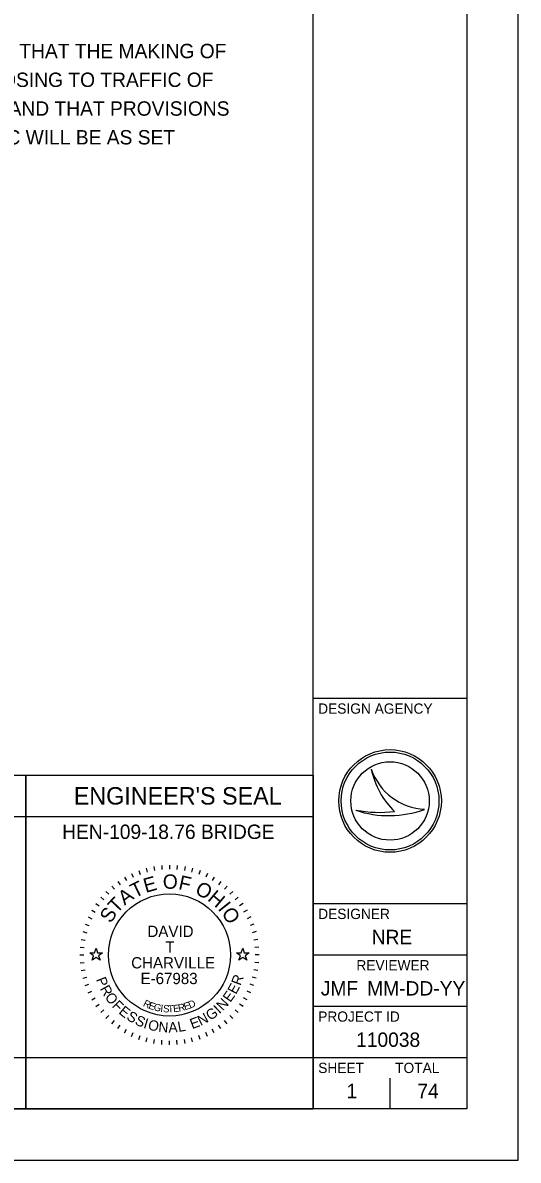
# Model space of a CAD drawing. Extents: x -6.2 to 37.4, y 0.2 to 22.2.
# Drawn here: x 28.75 to 33.58, y 0.21 to 11.29 of the extents above; entities that cross this region are included whole.
import ezdxf

# ---------------------------------------------------------------- set-up
doc = ezdxf.new("R2010")
doc.units = 0
for name, color, linetype in [('Default', 7, 'Continuous'), ('SH_Border', 7, 'Continuous'), ('SH_Cut_Line', 7, 'Continuous'), ('SH_Data', 7, 'Continuous'), ('SH_Text', 7, 'Continuous')]:
    doc.layers.add(name, color=color, linetype=linetype)

msp = doc.modelspace()

# ---------------------------------------------------------------- linework, layer by layer
at = {"layer": 'Default'}
for points in [[(29.404, 2.227), (29.451, 2.227), (29.466, 2.272), (29.48, 2.227), (29.527, 2.227), (29.489, 2.2), (29.504, 2.155), (29.466, 2.183), (29.428, 2.155), (29.442, 2.2)], [(30.834, 2.227), (30.881, 2.227), (30.896, 2.272), (30.91, 2.227), (30.957, 2.227), (30.919, 2.2), (30.934, 2.155), (30.896, 2.183), (30.858, 2.155), (30.872, 2.2)]]:
    msp.add_lwpolyline(points, close=True, dxfattribs=at)
at = {"layer": 'SH_Border'}
for p, q in [((31.581, 0.707), (31.581, 21.707)), ((31.581, 4.707), (33.081, 4.707)), ((31.581, 2.707), (33.081, 2.707)), ((31.581, 2.207), (33.081, 2.207)), ((31.581, 1.707), (33.081, 1.707)), ((31.581, 1.207), (33.081, 1.207))]:
    msp.add_line(p, q, dxfattribs=at)
msp.add_lwpolyline([(1.081, 21.707), (33.081, 21.707), (33.081, 0.707), (1.081, 0.707)], close=True, dxfattribs=at)
at = {"layer": 'SH_Cut_Line'}
msp.add_lwpolyline([(-0.419, 0.207), (33.581, 0.207), (33.581, 22.207), (-0.419, 22.207)], close=True, dxfattribs=at)
at = {"layer": 'SH_Data'}
for p, q in [((32.148, 4.017), (32.148, 4.017)), ((25.981, 3.957), (28.781, 3.957)), ((28.781, 3.957), (28.781, 0.707)), ((28.781, 0.707), (28.781, 3.957)), ((28.781, 3.957), (31.581, 3.957)), ((31.581, 3.957), (31.581, 0.707)), ((32.331, 3.707), (32.331, 3.707)), ((25.981, 3.557), (28.781, 3.557)), ((28.781, 3.557), (31.581, 3.557)), ((31.998, 3.617), (31.998, 3.617)), ((32.668, 3.626), (32.668, 3.626)), ((29.811, 3), (29.828, 2.964)), ((29.882, 3.03), (29.895, 2.992)), ((29.954, 3.053), (29.965, 3.014)), ((30.029, 3.069), (30.036, 3.03)), ((30.105, 3.079), (30.108, 3.039)), ((30.181, 3.082), (30.181, 3.042)), ((30.257, 3.079), (30.254, 3.039)), ((30.333, 3.069), (30.326, 3.03)), ((30.407, 3.053), (30.397, 3.014)), ((30.48, 3.03), (30.466, 2.992)), ((30.551, 3), (30.534, 2.964)), ((29.679, 2.924), (29.702, 2.891)), ((29.743, 2.965), (29.763, 2.931)), ((30.618, 2.965), (30.598, 2.931)), ((30.683, 2.924), (30.66, 2.891)), ((29.562, 2.826), (29.59, 2.798)), ((29.618, 2.878), (29.644, 2.847)), ((30.743, 2.878), (30.718, 2.847)), ((30.8, 2.826), (30.771, 2.798)), ((29.464, 2.709), (29.497, 2.686)), ((29.511, 2.77), (29.541, 2.744)), ((30.851, 2.77), (30.821, 2.744)), ((30.898, 2.709), (30.865, 2.686)), ((29.388, 2.577), (29.424, 2.56)), ((29.423, 2.645), (29.458, 2.625)), ((30.939, 2.645), (30.904, 2.625)), ((30.974, 2.577), (30.938, 2.56)), ((29.359, 2.507), (29.396, 2.493)), ((31.003, 2.507), (30.966, 2.493)), ((29.319, 2.359), (29.359, 2.352)), ((29.336, 2.434), (29.374, 2.424)), ((31.026, 2.434), (30.987, 2.424)), ((31.043, 2.359), (31.003, 2.352)), ((29.309, 2.284), (29.349, 2.28)), ((31.053, 2.284), (31.013, 2.28)), ((29.306, 2.207), (29.346, 2.207)), ((29.309, 2.131), (29.349, 2.135)), ((31.053, 2.131), (31.013, 2.135)), ((31.056, 2.207), (31.016, 2.207)), ((29.319, 2.055), (29.359, 2.062)), ((31.043, 2.055), (31.003, 2.062)), ((29.336, 1.981), (29.374, 1.991)), ((29.359, 1.908), (29.396, 1.922)), ((31.003, 1.908), (30.966, 1.922)), ((31.026, 1.981), (30.987, 1.991)), ((29.388, 1.838), (29.424, 1.855)), ((29.423, 1.77), (29.458, 1.79)), ((30.939, 1.77), (30.904, 1.79)), ((30.974, 1.838), (30.938, 1.855)), ((29.464, 1.706), (29.497, 1.728)), ((29.511, 1.645), (29.541, 1.671)), ((30.851, 1.645), (30.821, 1.671)), ((30.898, 1.706), (30.865, 1.728)), ((29.562, 1.589), (29.59, 1.617)), ((29.618, 1.537), (29.644, 1.568)), ((30.743, 1.537), (30.718, 1.568)), ((30.8, 1.589), (30.771, 1.617)), ((29.679, 1.491), (29.702, 1.523)), ((29.743, 1.45), (29.763, 1.484)), ((29.811, 1.414), (29.828, 1.451)), ((30.551, 1.414), (30.534, 1.451)), ((30.618, 1.45), (30.598, 1.484)), ((30.683, 1.491), (30.66, 1.523)), ((29.882, 1.385), (29.895, 1.423)), ((29.954, 1.362), (29.965, 1.401)), ((30.029, 1.346), (30.036, 1.385)), ((30.105, 1.336), (30.108, 1.376)), ((30.181, 1.332), (30.181, 1.372)), ((30.257, 1.336), (30.254, 1.376)), ((30.333, 1.346), (30.326, 1.385)), ((30.407, 1.362), (30.397, 1.401)), ((30.48, 1.385), (30.466, 1.423)), ((32.331, 0.707), (32.331, 1.007)), ((31.956, 0.882), (31.956, 0.882)), ((25.981, 0.707), (28.781, 0.707)), ((28.781, 0.707), (31.581, 0.707))]:
    msp.add_line(p, q, dxfattribs=at)
for points in [[(25.981, 0.707), (25.981, 1.207), (28.781, 1.207), (28.781, 0.707)], [(28.781, 0.707), (28.781, 1.207), (31.581, 1.207), (31.581, 0.707)]]:
    msp.add_lwpolyline(points, close=True, dxfattribs=at)
for centre, radius in [((32.331, 3.707), 0.5), ((32.331, 3.707), 0.477), ((32.331, 3.707), 0.477), ((32.331, 3.707), 0.382), ((30.181, 2.207), 0.595)]:
    msp.add_circle(centre, radius, dxfattribs=at)
for centre, radius, start, end in [((32.697, 4.205), 0.58, 198.9257, 198.9319), ((32.928, 4.177), 0.796, 191.6379, 191.6421), ((32.697, 4.205), 0.58, 198.9319, 267.1657), ((32.928, 4.177), 0.796, 191.6421, 226.0947), ((32.32, 4.577), 1.013, 251.4576, 290.0832), ((32.229, 4.862), 1.266, 259.4964, 259.4995), ((32.32, 4.577), 1.013, 251.4527, 251.4576), ((32.229, 4.862), 1.266, 259.4995, 276.6672)]:
    msp.add_arc(centre, radius, start, end, dxfattribs=at)

# ---------------------------------------------------------------- texts
for s, height, p in [('DESIGN AGENCY', 0.1, (31.631, 4.557)), ("ENGINEER'S SEAL", 0.17, (29.248, 3.672)), ('HEN-109-18.76 BRIDGE', 0.14, (29.135, 3.337)), ('DESIGNER', 0.1, (31.631, 2.557)), ('DAVID', 0.11, (29.966, 2.382)), ('NRE', 0.14, (32.152, 2.312)), ('T', 0.11, (30.14, 2.229)), ('CHARVILLE', 0.11, (29.808, 2.076)), ('REVIEWER', 0.1, (32.003, 2.057)), ('E-67983', 0.11, (29.899, 1.923)), ('JMF', 0.14, (31.656, 1.812)), ('MM-DD-YY', 0.14, (32.108, 1.812)), ('PROJECT ID', 0.1, (31.631, 1.557)), ('110038', 0.14, (32, 1.312)), ('SHEET', 0.1, (31.631, 1.057)), ('TOTAL', 0.1, (32.381, 1.057)), ('1', 0.14, (31.906, 0.812)), ('74', 0.14, (32.597, 0.812))]:
    msp.add_text(s, height=height, dxfattribs=at).set_placement(p)
for s, height, rotation, p in [('O', 0.14, 359.7812, (30.116, 2.852)), ('T', 0.14, 25.7167, (29.842, 2.759)), ('E', 0.14, 15.7571, (29.949, 2.811)), ('F', 0.14, 347.4362, (30.262, 2.849)), ('O', 0.14, 332.2586, (30.421, 2.809)), ('T', 0.14, 46.4344, (29.669, 2.604)), ('A', 0.14, 36.4747, (29.744, 2.686)), ('H', 0.14, 319.9136, (30.544, 2.744)), ('S', 0.14, 57.1924, (29.609, 2.509)), ('I', 0.14, 308.367, (30.647, 2.656)), ('O', 0.14, 303.1491, (30.683, 2.616)), ('P', 0.1, 291.494, (29.463, 1.969)), ('R', 0.1, 69.2322, (30.873, 1.903)), ('R', 0.1, 298.7311, (29.5, 1.879)), ('E', 0.1, 61.9951, (30.829, 1.817)), ('O', 0.1, 306.4666, (29.546, 1.796)), ('N', 0.1, 47.0224, (30.701, 1.658)), ('E', 0.1, 54.758, (30.774, 1.739)), ('F', 0.1, 314.7068, (29.615, 1.706)), ('E', 0.1, 321.4393, (29.679, 1.642)), ('R', 0.07, 334.487, (29.918, 1.712)), ('E', 0.07, 341.04, (29.971, 1.687)), ('G', 0.07, 347.4752, (30.022, 1.669)), ('I', 0.07, 353.7858, (30.09, 1.654)), ('S', 0.07, 356.8926, (30.117, 1.65)), ('T', 0.07, 3.0061, (30.167, 1.646)), ('E', 0.07, 6.0117, (30.22, 1.649)), ('R', 0.07, 11.9184, (30.273, 1.655)), ('E', 0.07, 17.6836, (30.331, 1.668)), ('D', 0.07, 23.3052, (30.382, 1.684)), ('G', 0.1, 35.0469, (30.579, 1.564)), ('I', 0.1, 43.287, (30.668, 1.629)), ('S', 0.1, 328.6764, (29.755, 1.583)), ('S', 0.1, 335.9134, (29.837, 1.534)), ('I', 0.1, 343.1505, (29.921, 1.497)), ('O', 0.1, 346.8859, (29.965, 1.483)), ('N', 0.1, 355.1261, (30.07, 1.459)), ('A', 0.1, 2.8617, (30.173, 1.451)), ('L', 0.1, 10.0987, (30.27, 1.456)), ('E', 0.1, 20.0742, (30.402, 1.484)), ('N', 0.1, 27.3113, (30.485, 1.515))]:
    msp.add_text(s, height=height, rotation=rotation, dxfattribs=at).set_placement(p)
at = {"layer": 'SH_Text'}
for s, p in [('I HEREBY APPROVE THESE PLANS AND DECLARE THAT THE MAKING OF', (24.109, 10.942)), ('THIS IMPROVEMENT WILL NOT REQUIRE THE CLOSING TO TRAFFIC OF', (24.109, 10.662)), ('THE HIGHWAY EXCEPT AS NOTED ON SHEET 19, AND THAT PROVISIONS', (24.109, 10.382)), ('FOR THE MAINTENANCE AND SAFETY OF TRAFFIC WILL BE AS SET', (24.109, 10.102))]:
    msp.add_text(s, height=0.14, dxfattribs=at).set_placement(p)

doc.saveas('drawing.dxf')
